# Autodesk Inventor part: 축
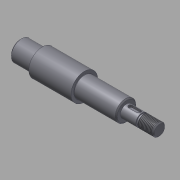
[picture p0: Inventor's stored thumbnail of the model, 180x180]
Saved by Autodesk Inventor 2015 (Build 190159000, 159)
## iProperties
Created: 2015-12
Part Number: 축
Material: 강철, 연강
Document SubType Name: Modeling
Designer: mdu
Density: 7.86 g/cm^3
Appearance: 강철
Author: mdu
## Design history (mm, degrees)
sketch "스케치5"
  geometry: L1 (0, 0)-(135, 0); L2 (0, 0)-(135, 0); L3 (135, 0)-(135, 6); L4 (103, 6)-(103, 10); L5 (103, 10)-(62, 10); L6 (62, 10)-(62, 13); L7 (62, 13)-(21, 13); L8 (21, 13)-(21, 10); L9 (21, 10)-(0, 10); L10 (0, 10)-(0, 0); L11 (118, 6)-(118, 5); L12 (118, 5)-(120, 5); L13 (120, 5)-(120, 6); L14 (135, 6)-(120, 6); L15 (118, 6)-(103, 6)
  constraints: 31 end point, 12 perpendicular, 9 parallel, 1 collinear, 1 horizontal
  dimensions: "d43" = 20 diameter of L9 L1; "d44" = 26 diameter of L7 L1; "d45" = 20 diameter of L5 L2; "d47" = 41 distance of L6.end L7.end; "d48" = 32 distance between parallel lines of L3 L4; "d50" = 21 distance of L8.end L9.end; "d52" = 12 diameter of L14 L1; "d53" = 15 distance between parallel lines of L3 L13; "d54" = 2 distance of L11.end L12.end; "d55" = 1 distance between parallel lines of L14 L12; "d64" = 135 distance of L1.start L1.end
revolve "회전4" sketch "스케치5" stored, may be unused: angle "d51" = 90 deg
feature "스레드6" dims "d56" = 10, "d57" = 0
chamfer "모따기6" distance "d32" = 1; stored, may be unused: second distance "d33" = 0.4, angle "d34" = 45 deg
chamfer "모따기5" distance "d27" = 1; stored, may be unused: second distance "d28" = 0.125, angle "d29" = 45 deg
fillet "모깎기1" dims "d17" = 0.3
fillet "모깎기2" dims "d18" = 0.3
chamfer "모따기3" distance "d19" = 1; stored, may be unused: second distance "d20" = 1, angle "d21" = 45 deg
node "작업 평면1"
sketch "스케치6"
  geometry: L1 (-3.5, 2)-(4.5, 2); L2 (4.5, -2)-(-3.5, -2); L3 (-7.5, 9)-(-7.5, -9) reference; A1 r 2 centre (4.5, 0) between (4.5, -2) and (4.5, 2); A2 r 2 centre (-3.5, 0) between (-3.5, 2) and (-3.5, -2); 1 further point
  constraints: 4 end point, 4 point on circle, 4 tangent, 2 centre point, 1 horizontal, 1 horizontal alignment, 1 parallel
  dimensions: "d59" = 2 distance edge to line of A2 L3; "d60" = 12 dimension on A1 A2; "d61" = 4 distance between parallel lines of L2 L1
extrude "돌출1" cut sketch "스케치6" distance "d62" = 2.3; taper "d63" = 0 deg
node "솔리드1"
node "솔리드2"
other parameters: "d46" = 12
